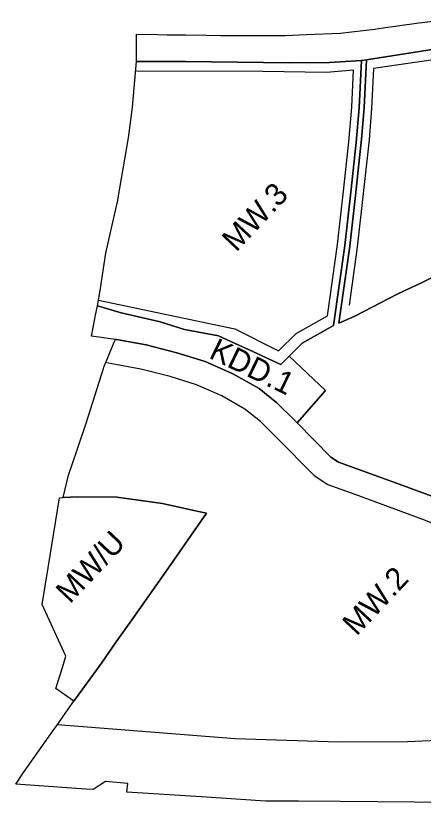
# Model space of a CAD drawing. Extents: x 7425782 to 7428854, y 5550411 to 5553074.
# Drawn here: x 7425781.5 to 7425945.6, y 5550411.4 to 5550728.8 of the extents above; entities that cross this region are included whole.
import ezdxf

# ---------------------------------------------------------------- set-up
doc = ezdxf.new("R2010")
doc.units = 0
for name, color, linetype in [('LIN_linie_rozgraniczajace', 7, 'Continuous'), ('LIN_nieprzekraczalna linia zabudowy', 7, 'Continuous'), ('TXT_oznaczenia przeznaczen', 7, 'Continuous')]:
    doc.layers.add(name, color=color, linetype=linetype)

msp = doc.modelspace()

# ---------------------------------------------------------------- linework, layer by layer
at = {"layer": 'LIN_linie_rozgraniczajace'}
for points in [[(7425950.06, 5550715.41), (7425922.75, 5550711.03), (7425922.75, 5550711.03), (7425920.73, 5550710.76), (7425907.86, 5550709.93), (7425891.74, 5550709.9), (7425849.86, 5550710.42), (7425830.22, 5550710.43), (7425830.23, 5550720.85), (7425830.23, 5550721.36), (7425838.56, 5550721.26), (7425842.45, 5550721.2), (7425849.95, 5550721.08), (7425858.34, 5550720.95), (7425863.93, 5550720.9), (7425868.22, 5550720.87), (7425868.91, 5550720.87), (7425878.49, 5550720.81), (7425885, 5550720.83), (7425886.48, 5550720.84), (7425886.48, 5550720.84), (7425887.35, 5550720.85), (7425890.11, 5550720.89), (7425898.44, 5550721.21), (7425912.29, 5550721.85), (7425916.68, 5550722.35), (7425926.16, 5550723.47), (7425927.62, 5550723.64), (7425927.62, 5550723.64), (7425943.9, 5550725.91), (7425949.57, 5550726.63)], [(7425955.3, 5550626.36), (7425945.26, 5550621.27), (7425935.44, 5550616.69), (7425918.13, 5550607.76), (7425911.69, 5550604.9), (7425916.01, 5550635.95), (7425918.49, 5550657.52), (7425920.02, 5550671.66), (7425920.82, 5550679.06), (7425921.82, 5550691.68), (7425922.75, 5550711.03), (7425950.06, 5550715.41)], [(7425949.04, 5550535.13), (7425933.38, 5550541), (7425911.51, 5550548.84), (7425908.44, 5550550.96), (7425894.82, 5550564.77), (7425906.29, 5550577.78), (7425891.67, 5550591.67), (7425896.89, 5550596.87), (7425909.54, 5550603.96), (7425914.03, 5550636.22), (7425916.5, 5550657.74), (7425918.67, 5550677.78), (7425919.83, 5550691.78), (7425920.73, 5550710.76), (7425922.75, 5550711.03), (7425922.75, 5550711.03), (7425921.82, 5550691.68), (7425920.82, 5550679.06), (7425920.02, 5550671.66), (7425918.49, 5550657.52), (7425916.01, 5550635.95), (7425911.69, 5550604.9), (7425918.13, 5550607.76), (7425935.44, 5550616.69), (7425945.26, 5550621.27), (7425955.3, 5550626.36)], [(7425980.47, 5550411.4), (7425942.1, 5550411.9), (7425942.1, 5550411.9), (7425912.11, 5550412.09), (7425895.37, 5550412.2), (7425882.11, 5550412.28), (7425856.28, 5550413.95), (7425856.24, 5550413.95), (7425856.24, 5550413.95), (7425826.31, 5550415.89), (7425826.63, 5550419.37), (7425817.67, 5550420.19), (7425812.67, 5550416.89), (7425809.77, 5550417.1), (7425781.63, 5550419.15), (7425781.55, 5550419.16), (7425784.72, 5550423.84), (7425797.27, 5550441.67), (7425797.77, 5550442.38), (7425802.71, 5550449.3), (7425804.99, 5550452.49), (7425816.01, 5550467.9), (7425817.77, 5550470.4), (7425822.02, 5550476.43), (7425828.65, 5550485.86), (7425843.01, 5550506.36), (7425858.4, 5550528.33), (7425853.19, 5550529.47), (7425840.69, 5550532.21), (7425822.24, 5550534.74), (7425806.29, 5550534.86), (7425800.69, 5550534.62), (7425802.83, 5550543.59), (7425806.33, 5550553.91), (7425809.94, 5550564.55), (7425816.92, 5550586.69), (7425817.07, 5550587.18), (7425817.07, 5550587.18), (7425821.23, 5550597.21), (7425821.77, 5550598.37), (7425821.77, 5550598.37), (7425822.15, 5550598.29), (7425834.06, 5550596.18), (7425846.47, 5550593.01), (7425857.8, 5550589.45), (7425868.98, 5550584.55), (7425879.51, 5550578.58), (7425886.68, 5550572.74), (7425893.48, 5550566.13), (7425894.82, 5550564.77), (7425908.44, 5550550.96), (7425911.51, 5550548.84), (7425933.38, 5550541), (7425949.04, 5550535.13)]]:
    msp.add_lwpolyline(points, dxfattribs=at)
for points in [[(7425920.73, 5550710.76), (7425919.83, 5550691.78), (7425918.67, 5550677.78), (7425916.5, 5550657.74), (7425914.03, 5550636.22), (7425909.54, 5550603.96), (7425896.89, 5550596.87), (7425891.67, 5550591.67), (7425888.29, 5550588.3), (7425885.34, 5550589.63), (7425876.99, 5550593.46), (7425869.83, 5550596.74), (7425863.25, 5550599.77), (7425849.43, 5550602.39), (7425839.65, 5550605.45), (7425824.05, 5550609.13), (7425814.4, 5550611.91), (7425814.4, 5550611.91), (7425815.53, 5550618.09), (7425817.87, 5550633.16), (7425821.34, 5550648.54), (7425822.55, 5550653.89), (7425823.46, 5550659.27), (7425826.9, 5550679.61), (7425826.9, 5550679.61), (7425827.43, 5550683.6), (7425828.4, 5550690.91), (7425828.5, 5550691.94), (7425830.22, 5550710.43), (7425849.86, 5550710.42), (7425891.74, 5550709.9), (7425907.86, 5550709.93)], [(7425885.34, 5550589.63), (7425888.29, 5550588.3), (7425891.67, 5550591.67), (7425906.29, 5550577.78), (7425894.82, 5550564.77), (7425893.48, 5550566.13), (7425886.68, 5550572.74), (7425879.51, 5550578.58), (7425868.98, 5550584.55), (7425857.8, 5550589.45), (7425846.47, 5550593.01), (7425834.06, 5550596.18), (7425822.15, 5550598.29), (7425821.77, 5550598.37), (7425812.02, 5550599.62), (7425813.38, 5550606.65), (7425813.54, 5550607.49), (7425814.4, 5550611.91), (7425814.4, 5550611.91), (7425814.4, 5550611.91), (7425824.05, 5550609.13), (7425839.65, 5550605.45), (7425849.43, 5550602.39), (7425863.25, 5550599.77), (7425869.83, 5550596.74), (7425876.99, 5550593.46)], [(7425816.01, 5550467.9), (7425804.99, 5550452.49), (7425802.18, 5550454.5), (7425797.68, 5550457.72), (7425800.33, 5550466.11), (7425801.77, 5550470.65), (7425792.86, 5550490.03), (7425792.16, 5550491.55), (7425794.55, 5550506.3), (7425799.14, 5550534.55), (7425800.69, 5550534.62), (7425806.29, 5550534.86), (7425822.24, 5550534.74), (7425840.69, 5550532.21), (7425853.19, 5550529.47), (7425858.4, 5550528.33), (7425843.01, 5550506.36), (7425828.65, 5550485.86), (7425822.02, 5550476.43), (7425817.77, 5550470.4)]]:
    msp.add_lwpolyline(points, close=True, dxfattribs=at)
at = {"layer": 'LIN_nieprzekraczalna linia zabudowy'}
msp.add_line((7425894.4, 5550600.74), (7425907.05, 5550607.82), dxfattribs=at)
for points in [[(7426025.85, 5550724.85), (7426025.1, 5550728.83), (7426005.63, 5550723.48), (7425979.6, 5550716.22), (7425959.87, 5550712.53), (7425925.59, 5550707.59)], [(7425917.55, 5550706.89), (7425906.73, 5550705.95), (7425881.01, 5550706.38), (7425830.22, 5550706.43)], [(7425907.05, 5550607.82), (7425911.05, 5550636.6), (7425913.51, 5550658.07), (7425915.68, 5550678.07), (7425916.83, 5550691.98), (7425917.55, 5550706.89)], [(7425925.59, 5550707.59), (7425924.82, 5550691.49), (7425923.8, 5550678.78), (7425921.47, 5550657.19), (7425918.99, 5550635.58), (7425915.74, 5550612.2)], [(7425814.82, 5550614.25), (7425869.77, 5550602.66), (7425875.43, 5550599.8), (7425881.14, 5550596.92), (7425887.4, 5550593.77), (7425894.4, 5550600.74)], [(7425963.83, 5550518.56), (7425945.46, 5550525.8), (7425918.16, 5550535.84), (7425906.9, 5550539.87), (7425901.98, 5550543.27), (7425886.44, 5550559.03), (7425880.03, 5550565.26), (7425873.84, 5550570.29), (7425864.49, 5550575.59), (7425854.28, 5550580.07), (7425843.73, 5550583.39), (7425831.95, 5550586.4), (7425820.21, 5550588.48), (7425817.82, 5550589)], [(7425798.29, 5550443.11), (7425869.88, 5550437.55), (7425911.5, 5550436.22), (7425939.3, 5550436.29), (7426006.01, 5550439.3)]]:
    msp.add_lwpolyline(points, dxfattribs=at)

# ---------------------------------------------------------------- texts
at = {"layer": 'TXT_oznaczenia przeznaczen'}
for s, rotation, p in [('MW.3', 46.7736, (7425870.32, 5550633.33)), ('KDD.1', 334.2209, (7425858.9, 5550591.1)), ('MW/U', 46.7967, (7425803.39, 5550491.53)), ('MW.2', 46.7736, (7425918.81, 5550478.51))]:
    msp.add_text(s, height=9, rotation=rotation, dxfattribs=at).set_placement(p)

doc.saveas('drawing.dxf')
